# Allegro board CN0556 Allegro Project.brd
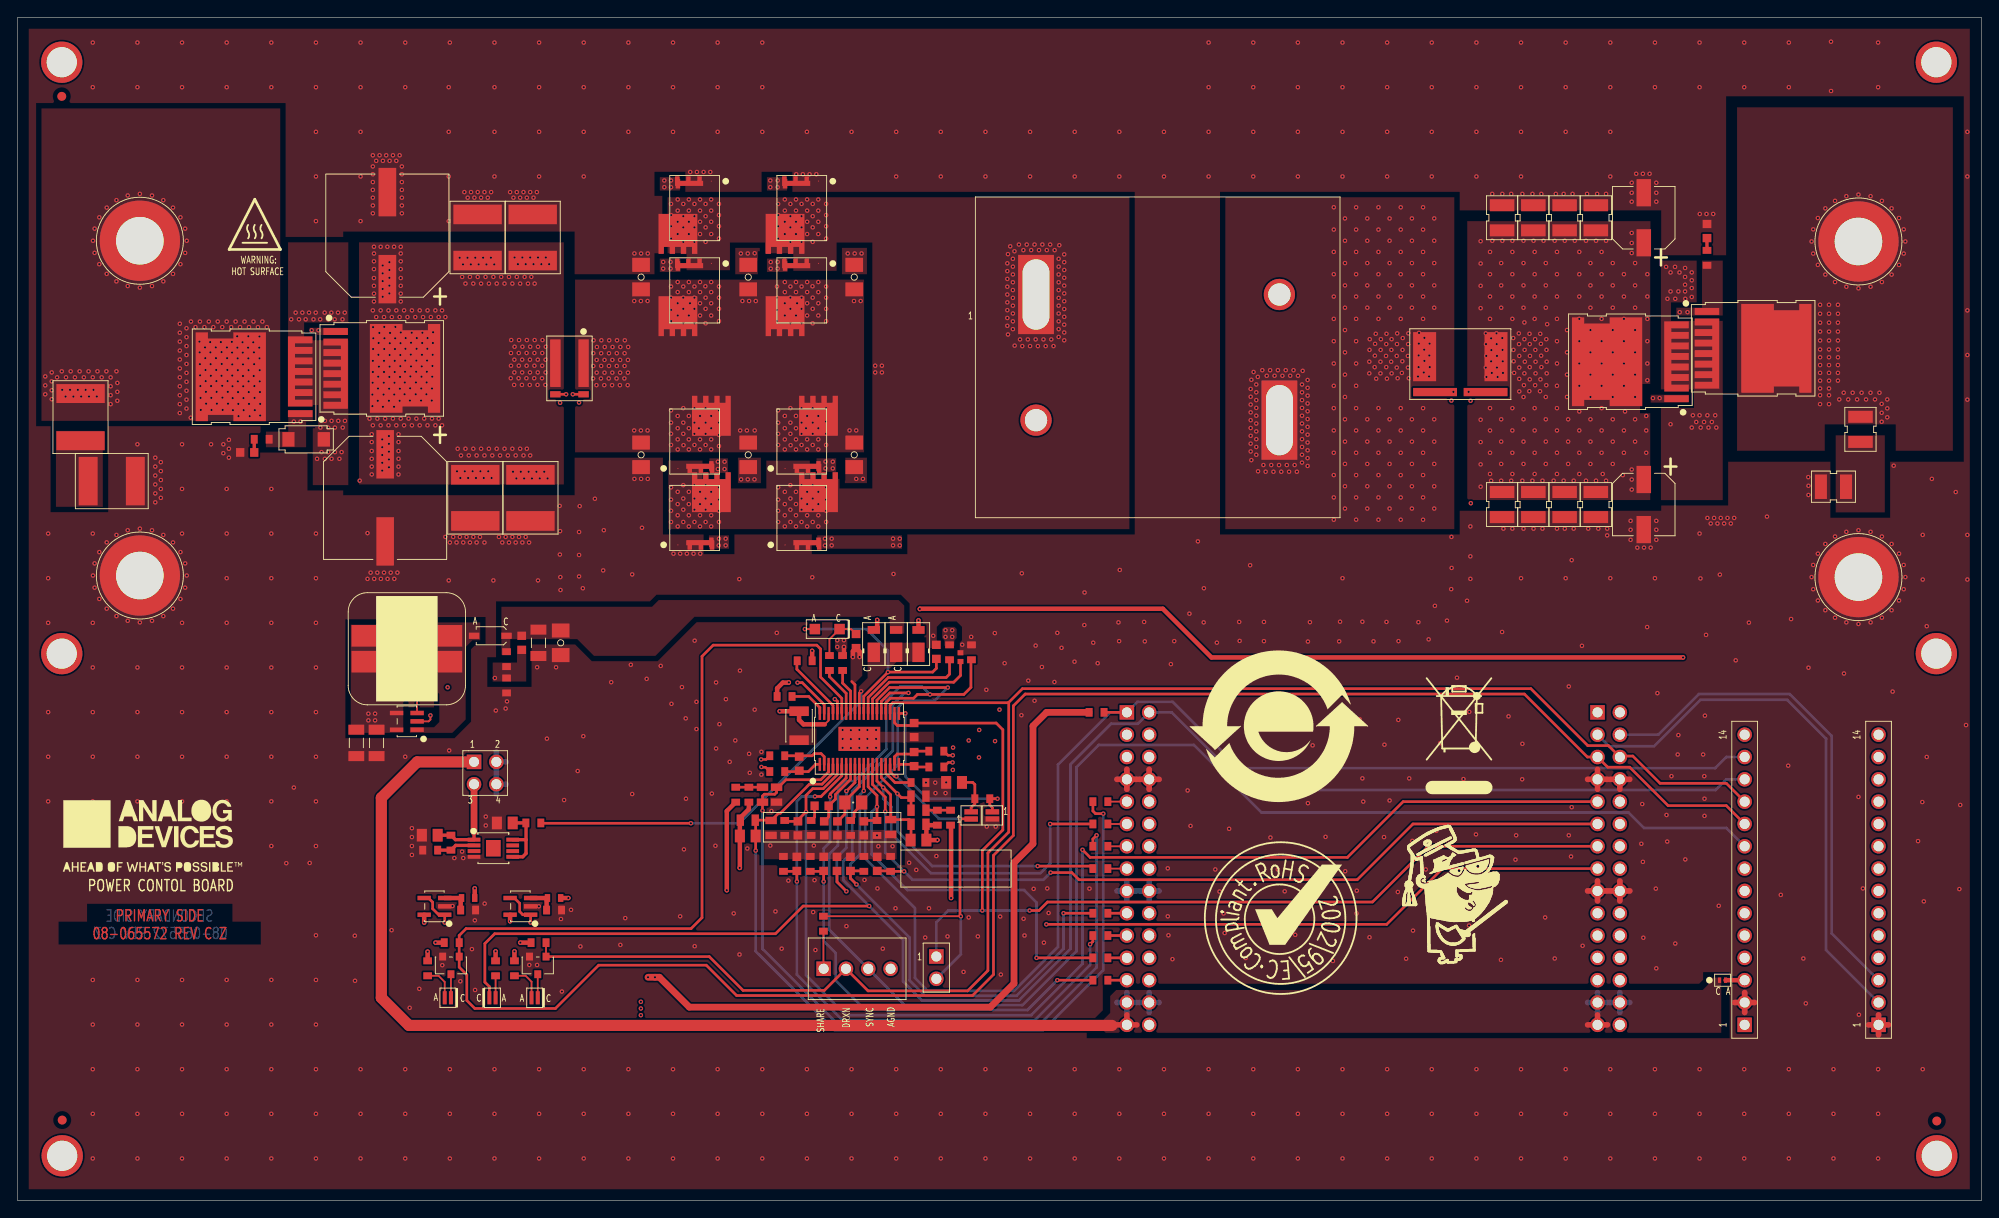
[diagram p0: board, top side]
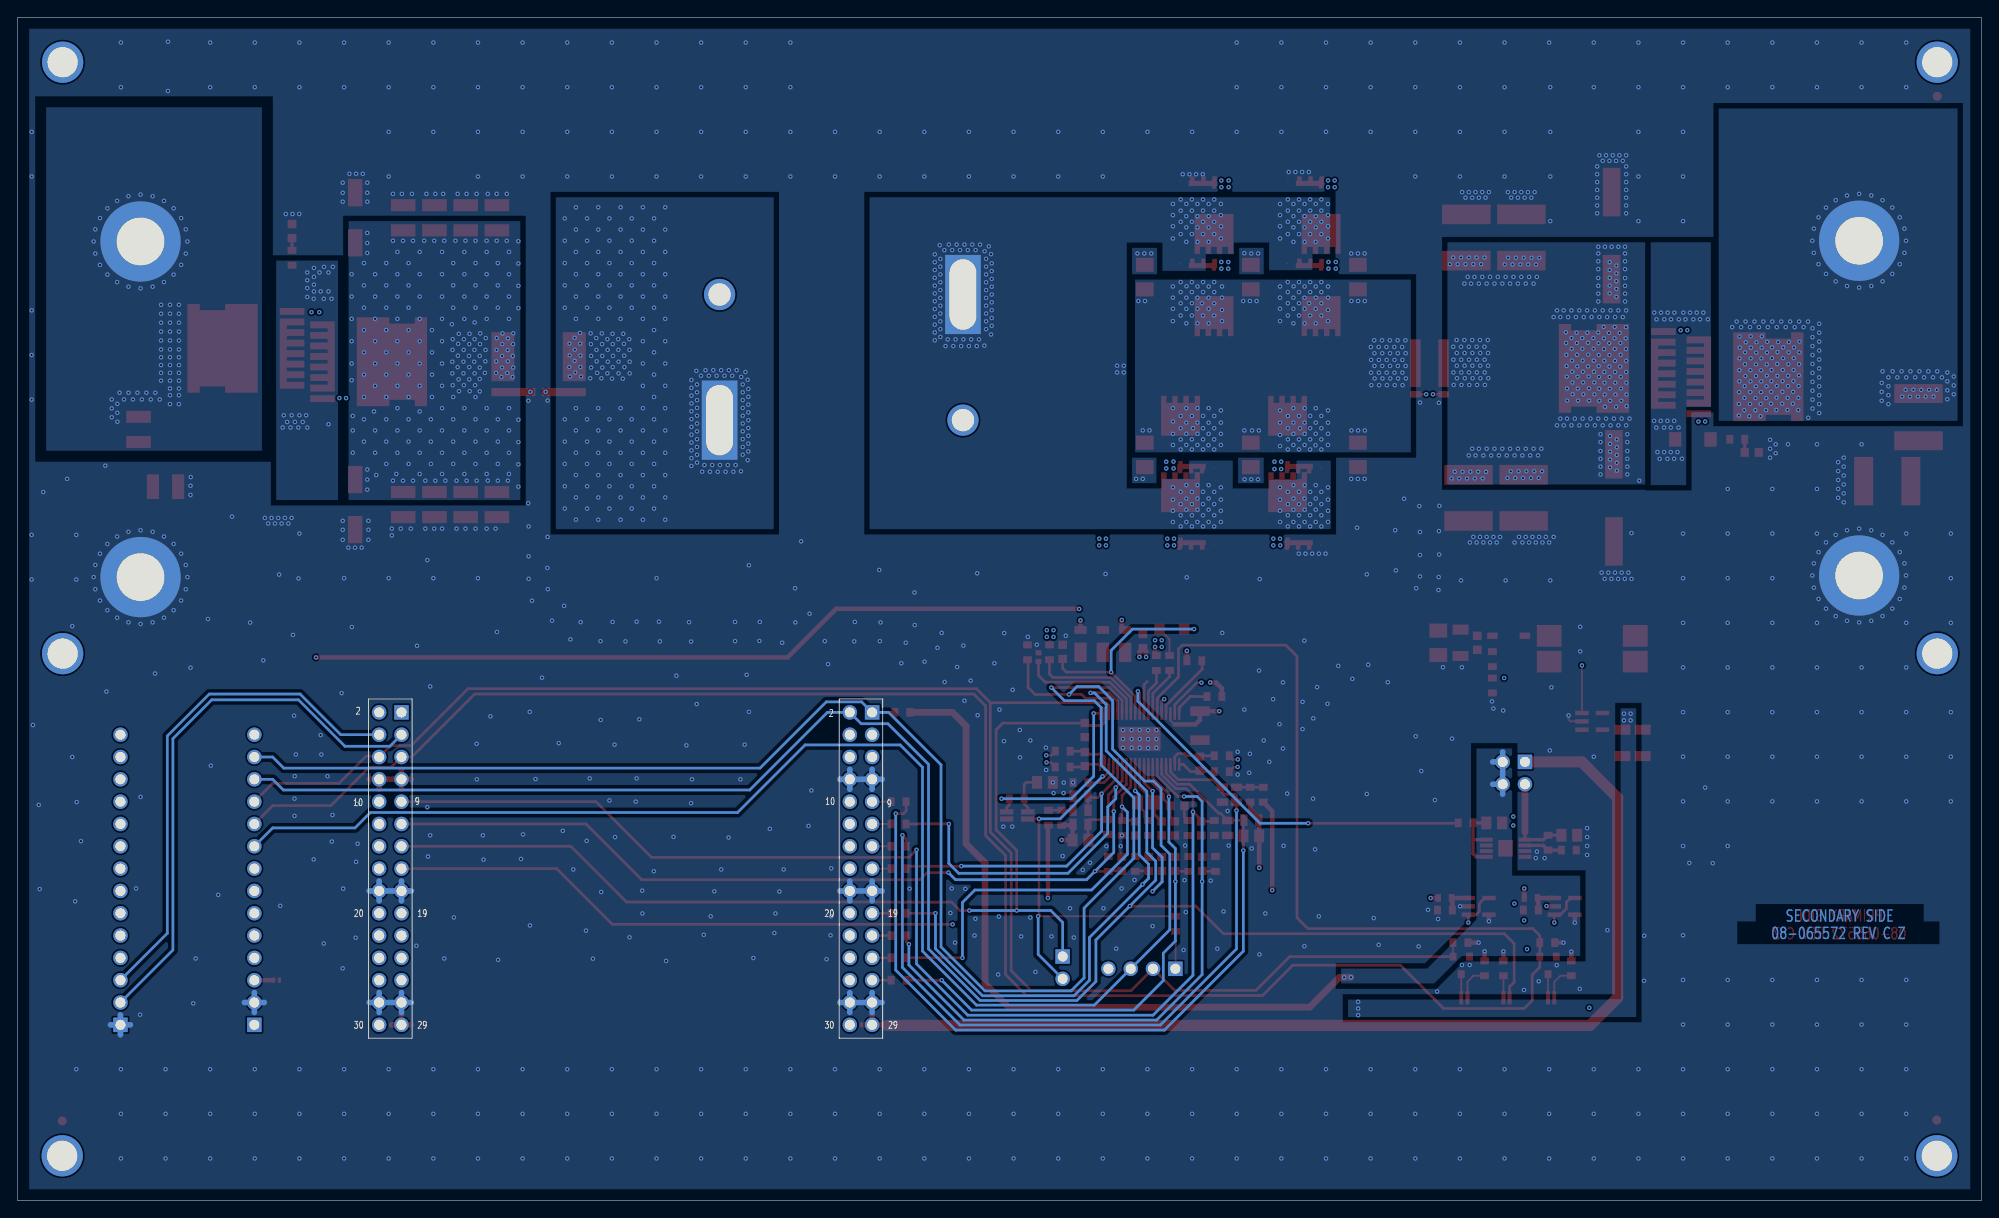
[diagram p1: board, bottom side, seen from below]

Outline 223.52 x 134.62 mm; copper layers: TOP, L2_GND, L3_PWR, BOTTOM. Coordinates in mm from the lower left corner of the outline.
Outline path: 0,134.62 0,0 223.52,0 223.52,134.62 0,134.62

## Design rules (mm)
constraint set DEFAULT: min track width 0.203
net group DP1_RSENSE1: nets UNNAMED_2_RES_I149_N1 UNNAMED_2_RES_I150_N1
net group DP2_RSENSE2: nets UNNAMED_2_RES_I147_N1 UNNAMED_2_RES_I148_N1
nets with their own width: min track width 0.203; nets UNNAMED_2_CAP_I281_N1

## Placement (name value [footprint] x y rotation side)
ADCCON  SSW-115-01-G-D  [CNRCPT2X15H335LD35]  179.83 55.55 270 bottom
BCKGND  575-4  [CNBANANAD312LD203]  209.52 70.94 0 top
BCKOUT  575-4  [CNBANANAD312LD203]  209.52 109.14 0 top
BSTGND  575-4  [CNBANANAD312LD203]  13.92 71.12 0 top
BSTOUT  575-4  [CNBANANAD312LD203]  13.92 109.22 0 top
C1  TBD  [C0603_0805]  83.11 41.48 0 top
C1N  0.01uF  [C0603]  88.7 38.3 90 top
C1P  0.01uF  [C0603]  94.79 38.3 90 top
C2  4.7uF  [C1210H87]  88.95 54.03 270 top
C2N  0.01uF  [C0603]  91.74 38.3 90 top
C2P  0.01uF  [C0603]  96.32 42.34 270 top
C3  1pF  [C0603]  88.96 49.71 90 top
C4  1pF  [C0603]  102.04 50.23 270 top
C5  1uF  [C0805]  55.45 42.96 180 top
C6  TBD  [C0603_0805]  102.54 41.01 180 top
C7  2.2uF  [C0805]  46.91 41.57 180 top
C8  2.2uF  [C1206]  38.56 52.07 270 top
C9  1uF  [C1206]  40.86 52.07 270 top
C10  10pF  [C0603]  57.38 63.46 270 top
C11  1uF  [C1206]  59.28 63.46 270 top
C12  4.7UF  [C1206H71]  61.82 63.46 270 top
CBST  0.1uF  [C0603]  95.43 63.67 90 top
CC1A  0.22uF  [C0603]  91.51 44.91 0 top
CC1B  220pF  [C0603]  91.82 42.34 90 top
CC2A  0.047uF  [C0805H60]  95.11 45.29 0 top
CC2B  470PF  [C0603]  93.32 42.34 270 top
CDG1  3300pF  [C0603]  26.14 85.13 180 top
CDG2  1000pF  [C0603]  192.28 110.32 90 top
CDM1_1  68UF  [CPLSMSQ531H551]  41.83 79.96 270 top
CDM1_2  68UF  [CPLSMSQ531H551]  42.09 109.8 90 top
CDM1_3  33UF  [CSML236W200H272]  52.36 109.59 270 top
CDM1_4  33UF  [CSML236W200H272]  58.63 109.59 90 top
CDM1_5  33UF  [CSML236W200H272]  52.1 79.96 90 top
CDM1_6  33UF  [CSML236W200H272]  58.38 79.96 270 top
CDM2_1  1uF  [C1206H71]  70.97 105.08 90 top
CDM2_2  1uF  [C1206H71]  83.16 105.08 90 top
CDM2_3  1uF  [C1206H71]  95.22 105.08 90 top
CDM2_4  1uF  [C1206H71]  70.97 84.86 270 top
CDM2_5  1uF  [C1206H71]  83.16 84.86 270 top
CDM2_6  1uF  [C1206H71]  95.22 84.86 270 top
CDM4_1  22UF  [C1210H110]  168.96 111.84 90 top
CDM4_2  22UF  [C1210H110]  172.52 111.84 90 top
CDM4_3  22UF  [C1210H110]  176.07 111.84 90 top
CDM4_4  22UF  [C1210H110]  179.63 111.84 90 top
CDM4_5  22UF  [C1210H110]  172.52 79.2 270 top
CDM4_6  22UF  [C1210H110]  168.96 79.2 270 top
CDM4_7  22UF  [C1210H110]  176.07 79.2 270 top
CDM4_8  22UF  [C1210H110]  179.63 79.2 270 top
CDM4_9  100uF  [CPLSMSQ260H315]  185.09 79.2 270 top
CDM4_X  100uF  [CPLSMSQ260H315]  185.09 111.84 90 top
CDRVCC  4.7uF  [C0603]  104.57 62.43 90 top
CINVCC  2.2uF  [C0603]  102.04 53.53 270 top
CMON1  0.01uF  [C0603]  88.81 42.34 270 top
CMON2  0.01uF  [C0603]  97.84 38.3 90 top
CSHARE  TBD  [C0603_0805]  106.59 47.57 180 top
CSS  0.1uF  [C0603]  93.27 38.3 90 top
CTMR  0.015uF  [C0402]  107.32 61.83 270 top
CV1_A  15uF  [C2220H264]  7.16 89.15 270 top
CV1_B  15uF  [C2220H264]  10.72 81.86 0 top
CV2_A  22UF  [C1210H110]  209.75 87.76 270 top
CV2_B  22UF  [C1210H110]  206.68 81.23 180 top
D1  DFLS1200Q-7  [POWERDI123]  100 63.32 90 top
D2  DFLS1200Q-7  [POWERDI123]  102.54 63.32 90 top
D3  DFLS1200Q-7  [POWERDI123]  97.46 63.32 90 top
D4  B0530W-7-F  [SOD123-3]  53.81 64.26 180 top
D5  BAT54LPS  [DFN2_1X0_6]  194.06 25.07 0 top
DACCON  SSW-115-01-G-D  [CNRCPT2X15H335LD35]  126.26 55.55 270 bottom
DBST  US1GWF-7  [SOD123F]  92.15 65.02 180 top
DS1  LXZ1-PM01  [LEDSML51W67H26]  48.97 23.06 180 top
DS2  LXZ1-PA01  [LEDSML51W67H26]  54.05 23.06 0 top
DS3  LXZ1-PB01  [LEDSML51W67H26]  58.85 23.06 180 top
DV1  SMAJ60CA  [DO214AC_C]  32.84 86.61 180 top
FB1CTL  11.3K  [R0603]  123.24 45.39 180 top
FB2CTL  8.66K  [R0603]  123.24 42.85 180 top
L1  10UH  [LTHL1417W1614H1378]  115.92 103.1 270 top
L2  10uH  [INDSUMCDRH125]  44.31 62.79 270 top
M1A  IPT007N06NATMA1  [HSOF8]  26.92 93.75 90 top
M1B  IPT007N06NATMA1  [HSOF8]  41.45 94.69 270 top
M2_1  IAUC70N08S5N074ATMA1  [SON8_FL]  77.06 86.37 0 top
M2_2  IAUC70N08S5N074ATMA1  [SON8_FL]  89.26 103.57 180 top
M2_3  IAUC70N08S5N074ATMA1  [SON8_FL]  77.06 103.57 180 top
M2_4  IAUC70N08S5N074ATMA1  [SON8_FL]  89.26 86.37 0 top
M3_1  IAUC70N08S5N074ATMA1  [SON8_FL]  77.06 77.67 0 top
M3_2  IAUC70N08S5N074ATMA1  [SON8_FL]  89.26 112.93 180 top
M3_3  IAUC70N08S5N074ATMA1  [SON8_FL]  77.06 112.93 180 top
M3_4  IAUC70N08S5N074ATMA1  [SON8_FL]  89.26 77.67 0 top
M4A  IPT007N06NATMA1  [HSOF8]  183.57 95.45 90 top
M4B  IPT007N06NATMA1  [HSOF8]  197.54 96.98 270 top
NOREF  -  []  -286.08 -132.38 0 top
NOREF#2  -  []  -106.07 273.65 0 top
NOREF#3  -  []  220.39 131.13 0 top
NOREF#4  -  []  -201.66 279.35 0 top
NOREF#5  -  []  67.11 26.24 0 top
NOREF#6  -  []  173.33 63.12 0 top
NOREF#7  -  []  0 0 0 top
NOREF#8  -  []  0 134.62 0 top
NOREF#9  -  []  -286.08 -132.38 0 top
NOREF#10  -  []  211.7 112.45 0 top
NOREF#11  -  []  55.75 267.72 0 top
NOREF#12  -  []  -107.56 263.49 0 top
NOREF#13  -  []  223.52 134.62 180 top
NOREF#14  -  []  143.51 53.97 0 top
NOREF#15  -  [unnamed#2]  5.03 62.23 0 top
NOREF#16  -  [unnamed#2]  218.44 5.08 0 top
NOREF#17  -  [unnamed#2]  5.03 129.54 0 top
NOREF#18  -  []  -25.45 -7.62 0 top
NOREF#19  -  []  48.97 19.94 0 top
NOREF#20  -  []  -201.81 273.65 0 top
NOREF#21  -  []  16.18 28.02 270 top
NOREF#22  -  []  5.08 5.08 0 top
NOREF#23  -  [unnamed#2]  218.39 129.54 0 top
NOREF#24  -  []  143.76 32 0 top
NOREF#25  -  []  223.52 0 90 top
NOREF#26  -  [unnamed#2]  218.44 9.04 0 top
NOREF#27  -  []  -25.45 -7.62 0 top
NOREF#28  -  []  5.08 5.08 0 top
NOREF#29  -  [unnamed#2]  5.08 9.14 0 top
NOREF#30  -  []  14.79 41.48 0 top
NOREF#31  -  []  243.89 279.6 0 top
NOREF#32  -  []  223.52 0 0 top
NOREF#33  -  []  -132.51 273.63 0 top
NOREF#34  -  []  223.52 0 90 top
NOREF#35  -  []  -75.36 268.55 0 top
NOREF#36  -  []  -286.08 -132.38 0 top
NOREF#37  -  []  0 0 0 top
NOREF#38  -  [unnamed#2]  5.03 125.65 0 top
NOREF#39  -  []  0 0 0 top
NOREF#40  -  []  261.8 64.47 0 top
NOREF#41  -  [unnamed#2]  5.08 5.08 0 top
NOREF#42  -  []  0 134.62 0 top
NOREF#43  -  []  119.3 364.57 0 top
NOREF#44  -  []  108.57 159.38 0 top
NOREF#45  -  [unnamed#2]  218.39 62.23 0 top
NOREF#46  -  []  -214.71 307.92 0 top
NOREF#47  -  []  -201.69 252.7 0 top
NOREF#48  -  []  0 134.62 270 top
NOREF#49  -  []  94.93 25.73 180 bottom
P1  TSW-102-07-T-D  [CNSAMTEC2X2H338LD36]  51.95 49.91 270 top
P2  SSQ-114-02-G-S  [CNTHFHDR1X14L1400W95H340]  211.81 19.99 90 top
P3  282834-4  [CN1X4H406]  95.55 26.37 0 top
P4  SSQ-114-02-G-S  [CNTHFHDR1X14L1400W95H340]  196.57 19.99 90 top
P5  TSW-102-07-G-S  [CNTHMHDR1X2L200W98H343]  104.57 27.76 270 top
P6  -  [JPSLD02]  108.53 43.81 90 top
P7  -  [JPSLD02]  110.95 43.81 270 top
Q1  2N7002-7-F  [SOT23-M3]  49.32 26.75 180 top
Q2  2N7002-7-F  [SOT23-M3]  59.21 26.75 180 top
R1  0  [R0603]  83.24 46.18 270 top
R1A  10K  [R0603]  51.28 33.05 0 top
R1B  243K  [R0603]  51.28 34.42 180 top
R1N  90.9K  [R0603]  87.17 38.3 90 top
R1P  90.9K  [R0603]  96.32 38.3 90 top
R2  0  [R0603]  81.74 46.18 270 top
R2A  10K  [R0603]  61.06 33.05 0 top
R2B  51K  [R0603]  61.06 34.42 180 top
R2N  26.1K  [R0603]  90.22 38.3 90 top
R2P  26.1K  [R0603]  97.82 42.39 270 top
R3  0  [R0603]  87.3 57.35 0 top
R4  0  [R0603]  91.72 31.5 90 top
R5  0  [R0603]  92.4 61.16 270 top
R6  1  [R0603]  106.07 62.38 270 top
R7  1  [R0603]  93.9 61.16 270 top
R8  0  [R0603]  89.59 61.42 0 top
R9  0  [R0603]  58.7 42.97 180 top
R10  499K  [R0603]  49.33 40.72 270 top
R11  316K  [R0603]  46.96 39.87 180 top
R13  0  [R0603]  106.19 43.56 90 top
R14  0  [R0603]  104.69 43.56 90 top
R16  115K  [R0603]  55.65 61.61 270 top
R17  13.3K  [R0603]  55.65 58.61 270 top
R22  4.99K  [R0603]  46.67 26.42 270 top
R23  6.65K  [R0603]  122.81 55.55 0 top
R24  1.21M  [R0603]  59.3 29.34 0 top
R25  4.99K  [R0603]  54.41 26.42 270 top
R26  22.1K  [R0603]  49.41 29.34 0 top
R27  4.99K  [R0603]  56.55 26.42 270 top
RC1  1K  [R0603]  90.32 42.39 90 top
RC2  1K  [R0603]  94.82 42.39 270 top
RCTL1N  665K  [R0603]  123.24 30.15 180 top
RCTL1P  665K  [R0603]  123.24 32.69 180 top
RCTL2N  187K  [R0603]  123.24 25.07 180 top
RCTL2P  187K  [R0603]  123.24 27.61 180 top
RDG1  10K  [R0603]  27.79 86.63 180 top
RDG2  10K  [R0603]  192.28 107.27 90 top
RFB1A  54.9K  [R0805]  83.11 43.28 0 top
RFB1B  1.21K  [R0805]  85.76 42.39 270 top
RFB2A  12.7K  [R0805]  102.54 42.81 180 top
RFB2B  1.21K  [R0805]  99.37 42.49 270 top
RIN1A  1.5K  [R0603]  86.46 48.81 0 top
RIN1B  1.5K  [R0603]  86.46 50.61 0 top
RIN2A  1.5K  [R0603]  104.57 51.13 180 top
RIN2B  1.5K  [R0603]  104.57 49.33 180 top
RMON1  187K  [R0603]  87.31 42.39 270 top
RMON2  53.6K  [R0603]  99.36 38.3 90 top
RSHARE  0  [R0603]  109.8 45.72 0 top
RSNS1  0.002  [R2512-4P]  62.81 94.69 270 top
RSNS2  0.002  [RSML260W396H123]  164.21 95.17 90 top
RSYNC  100K  [R0603]  108.57 62.38 90 top
RT  68K  [R0603]  102.54 47.56 0 top
RUV1A  52.3K  [R0805]  84.79 46.18 270 top
RUV1B  1.21K  [R0805]  86.39 46.18 270 top
RUV2A  10K  [R0805]  102.54 44.41 180 top
RUV2B  1.21K  [R0805]  102.54 46.01 0 top
U1  LT8228EFE#PBF  [TSSOP38_PAD4_75X2_74]  95.81 52.53 0 top
U2  LT3010EMS8E#PBF  [MSOP8_PAD1_88X1_68]  54.15 40.08 270 top
U3  LT1930ES5#TRPBF  [TSOT-5]  44.31 54.52 90 top
U4  ADA4505-1ARJZ  [SOT23-5L]  47.45 33.47 90 top
U5  ADA4505-1ARJZ  [SOT23-5L]  57.23 33.47 90 top
UV1CTL  10.2K  [R0603]  123.24 40.31 0 top
UV2CTL  8.2K  [R0603]  123.24 37.77 180 top

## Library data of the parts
ADCCON DACCON = CN30P_ODD_EVEN_V2: Tolerance: N/A; User Part Number: UPN; alternate symbols: (CNRCPT2X15H335LD35); part number: CN30P_ODD_EVEN_V2_TH-SSW-115-01-G-D,E012831,CNRCPT2X15H335LD35; tolerance: N/A
BCKGND BCKOUT BSTGND BSTOUT = CNTP1P: Tolerance: N/A; User Part Number: UPN; alternate symbols: (CNBANANAD312LD203); part number: CNTP1P_TH-575-4,E012555,CNBANANAD312LD203; tolerance: N/A
C1 C6 CSHARE = CAP: User Part Number: UPN; Tolerance: N/A; alternate symbols: (C0603_0805); part number: CAP_SM-TBD,N/A,N/A,E029810,C0603_0805; tolerance: N/A
C1N C1P C2N C2P CMON1 CMON2 = CAP: User Part Number: UPN; Tolerance: 10; alternate symbols: (C0603); part number: CAP_SM-0.01UF,50V,10,E038603,C0603; tolerance: 10
C2 = CAP: Tolerance: 10; User Part Number: UPN; alternate symbols: (C1210H87); part number: CAP_SM-4.7UF,100V,10,E023932,C1210H87; tolerance: 10
C3 C4 = CAP: User Part Number: UPN; Tolerance: 0.1pF; alternate symbols: (C0603); part number: CAP_SM-1PF,100V,0.1PF,E013795,C0603; tolerance: 0.1pF
C5 = CAP: User Part Number: UPN; Tolerance: 10; alternate symbols: (C0805); part number: CAP_SM-1UF,100V,10,E014208,C0805; tolerance: 10
C7 = CAP: User Part Number: UPN; Tolerance: 10; alternate symbols: (C0805); part number: CAP_SM-2.2UF,10V,10,E010425,C0805; tolerance: 10
C8 = CAP: User Part Number: UPN; Tolerance: 10; alternate symbols: (C1206); part number: CAP_SM-2.2UF,16V,10,E033858,C1206; tolerance: 10
C9 C11 = CAP: User Part Number: UPN; Tolerance: 10; alternate symbols: (C1206); part number: CAP_SM-1UF,25V,10,E029793,C1206; tolerance: 10
C10 = CAP: User Part Number: UPN; Tolerance: 5; alternate symbols: (C0603); part number: CAP_SM-10PF,50V,5,E031564,C0603; tolerance: 5
C12 = CAP: Tolerance: 10; User Part Number: UPN; alternate symbols: (C1206H71); part number: CAP_SM-4.7UF,16V,10,E042795,C1206H71; tolerance: 10
CBST = CAP: User Part Number: UPN; Tolerance: 10; alternate symbols: (C0603); part number: CAP_SM-0.1UF,50V,10,E031623,C0603; tolerance: 10
CC1A = CAP: User Part Number: UPN; Tolerance: 10; alternate symbols: (C0603); part number: CAP_SM-0.22UF,50V,10,E015565,C0603; tolerance: 10
CC1B = CAP: User Part Number: UPN; Tolerance: 5; alternate symbols: (C0603); part number: CAP_SM-220PF,50V,5,E042972,C0603; tolerance: 5
CC2A = CAP: Tolerance: 10; User Part Number: UPN; alternate symbols: (C0805H60); part number: CAP_SM-0.047UF,100V,10,E030859,C0805H60; tolerance: 10
CC2B = CAP: User Part Number: UPN; Tolerance: 10; alternate symbols: (C0603); part number: CAP_SM-470PF,25V,10,E044224,C0603; tolerance: 10
CDG1 = CAP: User Part Number: UPN; Tolerance: 10; alternate symbols: (C0603); part number: CAP_SM-3300PF,50V,10,E030855,C0603; tolerance: 10
CDG2 = CAP: User Part Number: UPN; Tolerance: 5; alternate symbols: (C0603); part number: CAP_SM-1000PF,100V,5,E012694,C0603; tolerance: 5
CDM1_1 CDM1_2 = CAPP: Tolerance: 20; User Part Number: UPN; alternate symbols: (CPLSMSQ531H551); part number: CAPP_SM-68UF,100V,20,E042912,CPLSMSQ531H551; tolerance: 20
CDM1_3-CDM1_6 = CAP: User Part Number: UPN; Tolerance: 22; alternate symbols: (CSML236W200H272); part number: CAP_SM-33UF,100V,22,E043544,CSML236W200H272; tolerance: 22
CDM2_1-CDM2_6 = CAP: Tolerance: 10; User Part Number: UPN; alternate symbols: (C1206H71); part number: CAP_SM-1UF,100V,10,E044891,C1206H71; tolerance: 10
CDM4_1-CDM4_8 CV2_A CV2_B = CAP: Tolerance: 20; User Part Number: UPN; alternate symbols: (C1210H110); part number: CAP_SM-22UF,25V,20,E044311,C1210H110; tolerance: 20
CDM4_9 CDM4_X = CAPP: Tolerance: 20; User Part Number: UPN; alternate symbols: (CPLSMSQ260H315); part number: CAPP_SM-100UF,25V,20,E027144,CPLSMSQ260H315; tolerance: 20
CDRVCC = CAP: User Part Number: UPN; Tolerance: 10; alternate symbols: (C0603); part number: CAP_SM-4.7UF,16V,10,E020112,C0603; tolerance: 10
CINVCC = CAP: User Part Number: UPN; Tolerance: 10; alternate symbols: (C0603); part number: CAP_SM-2.2UF,10V,10,E015288,C0603; tolerance: 10
CSS = CAP: User Part Number: UPN; Tolerance: 10; alternate symbols: (C0603); part number: CAP_SM-0.1UF,50V,10,E030853,C0603; tolerance: 10
CTMR = CAP: User Part Number: UPN; Tolerance: 10; alternate symbols: (C0402); part number: CAP_SM-0.015UF,35V,10,E033385,C0402; tolerance: 10
CV1_A CV1_B = CAP: User Part Number: UPN; Tolerance: 20; alternate symbols: (C2220H264); part number: CAP_SM-15UF,100V,20,E030670,C2220H264; tolerance: 20
D1-D3 = DIOSCHOTTKY: User Part Number: UPN; Tolerance: N/A; alternate symbols: (POWERDI123); part number: DIOSCHOTTKY_SM-DFLS1200Q-7,200V,N/A,E034778,POWERDI123; tolerance: N/A
D4 = DIOSCHOTTKY: Tolerance: N/A; User Part Number: UPN; alternate symbols: (SOD123-3); part number: DIOSCHOTTKY_SM-B0530W-7-F,30V,N/A,E014780,SOD123-3; tolerance: N/A
D5 = DIOSCHOTTKY: Tolerance: N/A; User Part Number: UPN; alternate symbols: (DFN2_1X0_6); part number: DIOSCHOTTKY_SM-BAT54LPS,30V,N/A,E023691,DFN2_1X0_6; tolerance: N/A
DBST = DIO: Tolerance: N/A; User Part Number: UPN; alternate symbols: (SOD123F); part number: DIO_SM-US1GWF-7,400V,N/A,E042975,SOD123F; tolerance: N/A
DS1 = DIOLED: User Part Number: UPN; Tolerance: N/A; alternate symbols: (LEDSML51W67H26); part number: DIOLED_SM-LXZ1-PM01,N/A,N/A,E024055,LEDSML51W67H26; tolerance: N/A
DS2 = DIOLED: User Part Number: UPN; Tolerance: N/A; alternate symbols: (LEDSML51W67H26); part number: DIOLED_SM-LXZ1-PA01,2.2V,N/A,E033979,LEDSML51W67H26; tolerance: N/A
DS3 = DIOLED: User Part Number: UPN; Tolerance: N/A; alternate symbols: (LEDSML51W67H26); part number: DIOLED_SM-LXZ1-PB01,2.85V,N/A,E033980,LEDSML51W67H26; tolerance: N/A
DV1 = DIOZNR_V2: User Part Number: UPN; Tolerance: 5; alternate symbols: (DO214AC_C); part number: DIOZNR_V2_SM-SMAJ60CA,60V,5,E044927,DO214AC_C; tolerance: 5
FB1CTL = RES: User Part Number: UPN; Tolerance: 1; alternate symbols: (R0603); part number: RES_SM-11.3K,E027487,1/10W,1,R0603; tolerance: 1
FB2CTL = RES: User Part Number: UPN; Tolerance: 1; alternate symbols: (R0603); part number: RES_SM-8.66K,E017718,1/10W,1,R0603; tolerance: 1
L1 = IND: Tolerance: 20; User Part Number: UPN; alternate symbols: (LTHL1417W1614H1378); part number: IND_TH-10UH,20,E043963,LTHL1417W1614H1378; tolerance: 20
L2 = IND_4P: Tolerance: 20; User Part Number: UPN; alternate symbols: (INDSUMCDRH125); part number: IND_4P_SM-10UH,20,E007395,INDSUMCDRH125; tolerance: 20
M1A M1B M4A M4B = TRANNMOSFET9P: User Part Number: UPN; Tolerance: N/A; alternate symbols: (HSOF8); part number: TRANNMOSFET9P_SM-IPT007N06NATMA1,E047026,HSOF8; tolerance: N/A
M2_1-M2_4 M3_1-M3_4 = TRANNMOSFET8P: Tolerance: N/A; User Part Number: UPN; alternate symbols: (SON8_FL); part number: TRANNMOSFET8P_SM-IAUC70N08S5N074ATMA1,E043073,SON8_FL; tolerance: N/A
P1 = CN4P_ODD_EVEN: User Part Number: UPN; Tolerance: N/A; alternate symbols: (CNSAMTEC2X2H338LD36); part number: CN4P_ODD_EVEN_TH-TSW-102-07-T-D,E032495,CNSAMTEC2X2H338LD36; tolerance: N/A
P2 P4 = CN14P: User Part Number: UPN; Tolerance: N/A; alternate symbols: (CNTHFHDR1X14L1400W95H340); part number: CN14P_TH-SSQ-114-02-G-S,E026120,CNTHFHDR1X14L1400W95H340; tolerance: N/A
P3 = CN4P: Tolerance: N/A; User Part Number: UPN; alternate symbols: (CN1X4H406); part number: CN4P_TH-282834-4,E016935,CN1X4H406; tolerance: N/A
P5 = CN2P: User Part Number: UPN; Tolerance: N/A; alternate symbols: (CNTHMHDR1X2L200W98H343); part number: CN2P_TH-TSW-102-07-G-S,E031850,CNTHMHDR1X2L200W98H343; tolerance: N/A
P6 P7 = NC2P: User Part Number: UPN; Tolerance: N/A; alternate symbols: (JPSLD02); part number: NC2P_SM-JPSLD02,E006230,JPSLD02; tolerance: N/A
Q1 Q2 = TRAN2N7002: User Part Number: UPN; Tolerance: N/A; alternate symbols: (SOT23-M3); part number: TRAN2N7002_SM-2N7002-7-F,E019273,SOT23-M3; tolerance: N/A
R1-R5 R8 R9 R13 R14 RSHARE = RES: User Part Number: UPN; Tolerance: JUMPER; alternate symbols: (R0603); part number: RES_SM-0,E006826,1/10W,JUMPER,R0603; tolerance: JUMPER
R1A R2A RDG1 RDG2 = RES: User Part Number: UPN; Tolerance: 1; alternate symbols: (R0603); part number: RES_SM-10K,E003671,1/10W,1,R0603; tolerance: 1
R1B = RES: User Part Number: UPN; Tolerance: 1; alternate symbols: (R0603L); part number: RES_SM-243K,E029637,1/10W,1,R0603; tolerance: 1
R1N R1P = RES: User Part Number: UPN; Tolerance: 1; alternate symbols: (R0603); part number: RES_SM-90.9K,E003723,1/10W,1,R0603; tolerance: 1
R2B = RES: User Part Number: UPN; Tolerance: 1; alternate symbols: (R0603L); part number: RES_SM-51K,E014698,1/10W,1,R0603; tolerance: 1
R2N R2P = RES: User Part Number: UPN; Tolerance: 1; alternate symbols: (R0603); part number: RES_SM-26.1K,E024699,1/10W,1,R0603; tolerance: 1
R6 R7 = RES: User Part Number: UPN; Tolerance: 5; alternate symbols: (R0603); part number: RES_SM-1,E011738,1/10W,5,R0603; tolerance: 5
R10 = RES: User Part Number: UPN; Tolerance: 1; alternate symbols: (R0603); part number: RES_SM-499K,E015340,1/10W,1,R0603; tolerance: 1
R11 = RES: User Part Number: UPN; Tolerance: 1; alternate symbols: (R0603); part number: RES_SM-316K,E027926,1/10W,1,R0603; tolerance: 1
R16 = RES: User Part Number: UPN; Tolerance: 1; alternate symbols: (R0603); part number: RES_SM-115K,E021375,1/10W,1,R0603; tolerance: 1
R17 = RES: User Part Number: UPN; Tolerance: 1; alternate symbols: (R0603); part number: RES_SM-13.3K,E008069,1/10W,1,R0603; tolerance: 1
R22 R25 R27 = RES: User Part Number: UPN; Tolerance: 1; alternate symbols: (R0603); part number: RES_SM-4.99K,E003726,1/10W,1,R0603; tolerance: 1
R23 = RES: User Part Number: UPN; Tolerance: 1; alternate symbols: (R0603); part number: RES_SM-6.65K,E023334,1/10W,1,R0603; tolerance: 1
R24 = RES: User Part Number: UPN; Tolerance: 1; alternate symbols: (R0603); part number: RES_SM-1.21M,E063409,1/10W,1,R0603; tolerance: 1
R26 = RES: User Part Number: UPN; Tolerance: 1; alternate symbols: (R0603); part number: RES_SM-22.1K,E003681,1/10W,1,R0603; tolerance: 1
RC1 RC2 = RES: User Part Number: UPN; Tolerance: 1; alternate symbols: (R0603); part number: RES_SM-1K,E003678,1/10W,1,R0603; tolerance: 1
RCTL1N RCTL1P = RES: User Part Number: UPN; Tolerance: 1; alternate symbols: (R0603); part number: RES_SM-665K,E063003,1/10W,1,R0603; tolerance: 1
RCTL2N RCTL2P RMON1 = RES: User Part Number: UPN; Tolerance: 1; alternate symbols: (R0603); part number: RES_SM-187K,E032773,1/10W,1,R0603; tolerance: 1
RFB1A = RES: User Part Number: UPN; Tolerance: 1; alternate symbols: (R0805L); part number: RES_SM-54.9K,E033779,1/8W,1,R0805; tolerance: 1
RFB1B RFB2B RUV1B RUV2B = RES: User Part Number: UPN; Tolerance: 1; alternate symbols: (R0805L); part number: RES_SM-1.21K,E003483,1/8W,1,R0805; tolerance: 1
RFB2A = RES: User Part Number: UPN; Tolerance: 1; alternate symbols: (R0805L); part number: RES_SM-12.7K,E015005,1/8W,1,R0805; tolerance: 1
RIN1A RIN1B RIN2A RIN2B = RES: User Part Number: UPN; Tolerance: 1; alternate symbols: (R0603); part number: RES_SM-1.5K,E003704,1/10W,1,R0603; tolerance: 1
RMON2 = RES: User Part Number: UPN; Tolerance: 1; alternate symbols: (R0603); part number: RES_SM-53.6K,E027826,1/10W,1,R0603; tolerance: 1
RSNS1 = RES4PKEL_V6: User Part Number: UPN; Tolerance: 2; alternate symbols: (R2512-4P); part number: RES4PKEL_V6_SM-0.002,E063408,2W,2,R2512-4P; tolerance: 2
RSNS2 = RES4PKEL_V7: Tolerance: 1; User Part Number: UPN; alternate symbols: (RSML260W396H123_A); part number: RES4PKEL_V7_SM-0.002,E043111,4W,1,RSML260W396H123; tolerance: 1
RSYNC = RES: User Part Number: UPN; Tolerance: 1; alternate symbols: (R0603); part number: RES_SM-100K,E010279,1/10W,1,R0603; tolerance: 1
RT = RES: User Part Number: UPN; Tolerance: 1; alternate symbols: (R0603); part number: RES_SM-68K,E031013,1/10W,1,R0603; tolerance: 1
RUV1A = RES: User Part Number: UPN; Tolerance: 1; alternate symbols: (R0805L); part number: RES_SM-52.3K,E028373,1/8W,1,R0805; tolerance: 1
RUV2A = RES: User Part Number: UPN; Tolerance: 1; alternate symbols: (R0805L); part number: RES_SM-10K,E003254,1/8W,1,R0805; tolerance: 1
U1 = ADLT8228: User Part Number: UPN; Tolerance: N/A; alternate symbols: (TSSOP38_PAD4_75X2_74); part number: ADLT8228_SM-LT8228EFE#PBF,E045130,TSSOP38_PAD4_75X2_74; tolerance: N/A
U2 = ADLT3010: Tolerance: N/A; User Part Number: UPN; alternate symbols: (MSOP8_PAD1_88X1_68); part number: ADLT3010_SM-LT3010EMS8E#PBF,E043304,MSOP8_PAD1_88X1_68; tolerance: N/A
U3 = LINLT1930: User Part Number: UPN; Tolerance: N/A; alternate symbols: (TSOT-5); part number: LINLT1930_SM-LT1930ES5#TRPBF,E030333,TSOT-5; tolerance: N/A
U4 U5 = AD8677: User Part Number: UPN; Tolerance: N/A; alternate symbols: (SOT23-5L); part number: AD8677_SM-ADA4505-1ARJZ,E015633,SOT23-5L; tolerance: N/A
UV1CTL = RES: User Part Number: UPN; Tolerance: 1; alternate symbols: (R0603); part number: RES_SM-10.2K,E013703,1/10W,1,R0603; tolerance: 1
UV2CTL = RES: User Part Number: UPN; Tolerance: 1; alternate symbols: (R0603); part number: RES_SM-8.2K,E042863,1/10W,1,R0603; tolerance: 1

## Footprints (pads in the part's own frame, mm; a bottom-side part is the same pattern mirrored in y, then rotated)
C0402
  rect 0.584x0.66 smd: 1(-0.5,0) 2(0.5,0)
C0603
  rect 0.94x0.991 smd: 1(-0.8,0) 2(0.8,0)
C0603_0805
  rect 1.143x1.448 smd: 1(-0.9,0) 2(0.9,0)
C0805
  rect 1.143x1.448 smd: 1(-0.9,0) 2(0.9,0)
C0805H60
  rect 1.295x1.6 smd: 1(-0.953,0) 2(0.953,0)
C1206
  rect 1.143x1.803 smd: 1(-1.5,0) 2(1.5,0)
C1206H71
  rect 1.6x2.007 smd: 1(-1.397,0) 2(1.397,0)
C1210H87
  rect 1.092x2.21 smd: 1(-1.646,0) 2(1.646,0)
C1210H110
  rect 1.372x2.794 smd: 1(-1.431,0) 2(1.431,0)
C2220H264
  rect 2.159x5.512 smd: 1(-2.685,0) 2(2.685,0)
CN1X4H406
  rect 1.651x1.651 hole 1.143: 1(-3.81,0)
  round 1.651 hole 1.143: 2(-1.27,0) 3(1.27,0) 4(3.81,0)
CNBANANAD312LD203
  round 9.144 hole 5.41: 1(0,0)
CNRCPT2X15H335LD35
  rect 1.651x1.651 hole 1.143: 1(0,0)
  round 1.651 hole 1.143: 2(0,-2.54) 3(2.54,0) 4(2.54,-2.54) 5(5.08,0) 6(5.08,-2.54) 7(7.62,0) 8(7.62,-2.54) 9(10.16,0) 10(10.16,-2.54) 11(12.7,0) 12(12.7,-2.54) 13(15.24,0) 14(15.24,-2.54) 15(17.78,0) 16(17.78,-2.54) 17(20.32,0) 18(20.32,-2.54) 19(22.86,0) 20(22.86,-2.54) 21(25.4,0) 22(25.4,-2.54) 23(27.94,0) 24(27.94,-2.54) 25(30.48,0) 26(30.48,-2.54) 27(33.02,0) 28(33.02,-2.54) 29(35.56,0) 30(35.56,-2.54)
CNSAMTEC2X2H338LD36
  rect 1.651x1.651 hole 1.143: 1(0,0)
  round 1.651 hole 1.143: 2(0,2.54) 3(2.54,0) 4(2.54,2.54)
CNTHFHDR1X14L1400W95H340
  rect 1.651x1.651 hole 1.143: 1(0,0)
  round 1.651 hole 1.143: 2(2.54,0) 3(5.08,0) 4(7.62,0) 5(10.16,0) 6(12.7,0) 7(15.24,0) 8(17.78,0) 9(20.32,0) 10(22.86,0) 11(25.4,0) 12(27.94,0) 13(30.48,0) 14(33.02,0)
CNTHMHDR1X2L200W98H343
  rect 1.651x1.651 hole 1.143: 1(0,0)
  round 1.651 hole 1.143: 2(2.54,0)
CPLSMSQ260H315
  rect 3.099x1.651 smd: N(2.85,0) P(-2.85,0)
CPLSMSQ531H551
  rect 5.512x2.007 smd: N(4.956,0) P(-4.956,0)
CSML236W200H272
  rect 2.235x5.512 smd: 1(-2.628,0) 2(2.628,0)
DFN2_1X0_6
  rect 0.356x0.61 smd: A(0.34,0) C(-0.34,0)
DO214AC_C
  rect 1.397x1.651 smd: 1(-2.013,0) 2(2.013,0)
HSOF8
  rect 0.787x2.794 smd: 1(-4.2,-5.253)
  round 0.254 smd: 2(-3,-5.253) 3(-1.8,-5.253) 4(-0.6,-5.253) 6(1.8,-5.253) 7(3,-5.253) 8(4.2,-5.253)
  custom 0.699x0.699 smd: 5(0.6,-5.253)
  custom 2x2 smd: 9(0,2.649)
INDSUMCDRH125
  rect 2.464x2.819 smd: 1(-1.469,-4.897) 2(1.469,-4.897) 3(1.469,4.897) 4(-1.469,4.897)
JPSLD02
  rect 0.61x1.549 smd: 1(-0.406,0) 2(0.406,0)
LEDSML51W67H26
  rect 0.457x1.499 smd: A(0.354,0) C(-0.354,0)
LTHL1417W1614H1378
  round 3.556 hole 2.54: (0,27.7) (14.3,0)
  rect 9.017x4.064 hole 8.001x3.048: 1(0,0) 2(14.3,27.7)
MSOP8_PAD1_88X1_68
  rect 0.457x1.448 smd: 1(-0.975,-2.2) 2(-0.325,-2.2) 3(0.325,-2.2) 4(0.975,-2.2) 5(0.975,2.2) 6(0.325,2.2) 7(-0.325,2.2) 8(-0.975,2.2)
  rect 1.88x1.676 smd: PAD(0,0)
POWERDI123
  rect 0.889x1.397 smd: A(1.606,0)
  rect 2.21x1.397 smd: C(-0.945,0)
R0603
  rect 0.787x0.991 smd: 1(-0.85,0) 2(0.85,0)
R0805
  rect 0.838x1.295 smd: 1(-0.85,0) 2(0.85,0)
R2512-4P
  rect 5.41x1.194 smd: 1(-0.595,1.603) 2(-0.595,-1.603)
  rect 0.711x1.194 smd: 3(2.944,1.603) 4(2.944,-1.603)
RSML260W396H123
  rect 5.588x2.616 smd: F1(0.851,-4.064) F2(0.851,4.064)
  rect 0.94x4.991 smd: S1(-3.175,-2.875) S2(-3.175,2.875)
SOD123-3
  rect 1.194x0.711 smd: A(1.847,0) C(-1.847,0)
SOD123F
  rect 1.194x1.194 smd: A(1.403,0) C(-1.403,0)
SON8_FL
  round 0.127 smd: 1(-1.905,-3.071) 2(-0.635,-3.071) 6(0.635,2.931) 7(-0.635,2.931) 8(-1.905,2.931)
  custom 0.273x0.273 smd: 3(0.635,-3.071)
  rect 0.508x1.092 smd: 4(1.905,-2.779)
  custom 1.105x1.105 smd: 5(1.905,2.931)
SOT23-5L
  rect 0.508x1.524 smd: 1(-0.95,-1.17) 2(0,-1.17) 3(0.95,-1.17) 4(0.95,1.17) 5(-0.95,1.17)
SOT23-M3
  rect 0.787x0.889 smd: 1(-0.94,-1.003) 2(0.94,-1.003) 3(0,1.003)
TSOT-5
  rect 0.508x1.524 smd: 1(-0.95,-1.17) 2(0,-1.17) 3(0.95,-1.17) 4(0.95,1.17) 5(-0.95,1.17)
TSSOP38_PAD4_75X2_74
  rect 0.279x1.473 smd: 1(-4.5,-2.9) 2(-4,-2.9) 3(-3.5,-2.9) 4(-3,-2.9) 5(-2.5,-2.9) 6(-2,-2.9) 7(-1.5,-2.9) 8(-1,-2.9) 9(-0.5,-2.9) 10(0,-2.9) 11(0.5,-2.9) 12(1,-2.9) 13(1.5,-2.9) 14(2,-2.9) 15(2.5,-2.9) 16(3,-2.9) 17(3.5,-2.9) 18(4,-2.9) 19(4.5,-2.9) 20(4.5,2.9) 21(4,2.9) 22(3.5,2.9) 23(3,2.9) 24(2.5,2.9) 25(2,2.9) 26(1.5,2.9) 27(1,2.9) 28(0.5,2.9) 29(0,2.9) 30(-0.5,2.9) 31(-1,2.9) 32(-1.5,2.9) 33(-2,2.9) 34(-2.5,2.9) 35(-3,2.9) 36(-3.5,2.9) 37(-4,2.9) 38(-4.5,2.9)
  rect 4.75x2.743 smd: PAD(0,0)
unnamed#2
  round 4.699 hole 3.429 unplated: (0,0)

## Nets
3V3: P1.2 P1.4(N4) R22.1 R23.1 R24.1 R25.1 R26.1 R27.1 U4.5 U5.5
12V: C10.1 C11.1 C12.1 D1.A(P) D4.C R16.1
AGND: ADCCON.7 ADCCON.8 ADCCON.17 ADCCON.18(N9) ADCCON.27 ADCCON.28 BCKGND.1(N1) BSTGND.1(N1) C1N.2(N2) C1P.2(N2) C2.2(N2) C2N.2(N2) C2P.2(N2) C5.2(N2) C7.2(N2) C8.2(N2) C9.2(N2) C11.2(N2) C12.2(N2) CC1B.1 CC2B.2(N2) CDG1.2(N2) CDG2.2(N2) CDM1_1.N(N2) CDM1_2.N(N2) CDM1_3.1 CDM1_4.2(N2) CDM1_5.1 CDM1_6.2(N2) CDM2_1.2(N2) CDM2_2.2(N2) CDM2_3.2(N2) CDM2_4.2(N2) CDM2_5.2(N2) CDM2_6.2(N2) CDM4_1.2(N2) CDM4_2.2(N2) CDM4_3.2(N2) CDM4_4.2(N2) CDM4_5.2(N2) CDM4_6.2(N2) CDM4_7.2(N2) CDM4_8.2(N2) CDM4_9.N(N2) CDM4_X.N(N2) CDRVCC.2(N2) CINVCC.2(N2) CMON1.2(N2) CMON2.2(N2) CSHARE.2(N2) CSS.2(N2) CTMR.1 CV1_B.2(N2) CV2_B.2(N2) DACCON.7 DACCON.8 DACCON.17 DACCON.18(N9) DACCON.27 DACCON.28 M3_1.1 M3_1.2 M3_1.3(S3) M3_2.1 M3_2.2 M3_2.3(S3) M3_3.1 M3_3.2 M3_3.3(S3) M3_4.1 M3_4.2 M3_4.3(S3) P2.1 P3.4(N4) P4.2 P7.2(N2) Q1.2(S) Q2.2(S) R1A.2(N2) R1N.2(N2) R1P.2(N2) R2A.2(N2) R2N.2(N2) R2P.2(N2) R11.2(N2) R17.2(N2) RC1.1 RC2.2(N2) RFB1B.2(N2) RFB2B.2(N2) RMON1.2(N2) RMON2.2(N2) RSYNC.2(N2) RT.2(N2) RUV1B.2(N2) RUV2B.2(N2) U1.PAD U2.4 U3.2 U4.2(V-) U5.2(V-)
V1_ADC: ADCCON.19 U4.1 U4.4
V1D: C1.1 C2.1 CDM1_1.P CDM1_2.P CDM1_3.2(N2) CDM1_4.1 CDM1_5.2(N2) CDM1_6.1 M1B.9 R1.2(N2) RFB1A.1 RSNS1.2 U1.36
V2_ADC: ADCCON.23 U5.1 U5.4
V2D: C6.1 CDM4_1.1 CDM4_2.1 CDM4_3.1 CDM4_4.1 CDM4_5.1 CDM4_6.1 CDM4_7.1 CDM4_8.1 CDM4_9.P CDM4_X.P M4A.9 R14.1 RFB2A.1 RSNS2.F1
BG: M3_1.4 M3_2.4 M3_3.4 M3_4.4 R6.1
BIAS: D1.C D2.C D3.C R9.1 U1.29
BOOSTOUT: BSTOUT.1(N1) CV1_A.1 D3.A(P) M1A.9 R1B.1 R2.2(N2)
BUCKOUT: BCKOUT.1(N1) CV2_A.1 D2.A(P) M4B.9 R2B.1 R13.1
DG1: DV1.2(N2) M1A.1 M1B.1 R3.1 RDG1.1
DG2: M4A.1 M4B.1 R8.2(N2) RDG2.1
DRXN: ADCCON.6 P3.2 P4.11 Q2.1 R24.2(N2) U1.22
DS1: DV1.1 M1A.2 M1A.3 M1A.4 M1A.5 M1A.6 M1A.7 M1A.8(S7) M1B.2 M1B.3 M1B.4 M1B.5 M1B.6 M1B.7 M1B.8(S7) U1.37
DS2: M4A.2 M4A.3 M4A.4 M4A.5 M4A.6 M4A.7 M4A.8(S7) M4B.2 M4B.3 M4B.4 M4B.5 M4B.6 M4B.7 M4B.8(S7) U1.34
EN: ADCCON.5 P4.10 Q1.1 R26.2(N2) U1.33
EXTPWR: ADCCON.29 D5.C DACCON.29 P1.1
FAULT: DACCON.2 DS2.C P4.12 U1.24
FB1: C1.2(N2) FB1CTL.2(N2) RFB1A.2(N2) RFB1B.1 U1.4
FB1_CTL: DACCON.9 FB1CTL.1
FB2: C6.2(N2) FB2CTL.2(N2) RFB2A.2(N2) RFB2B.1 U1.14
FB2_CTL: DACCON.11 FB2CTL.1
IMON1: ADCCON.9 CMON1.1 RMON1.1 U1.5
IMON2: ADCCON.11 CMON2.1 RMON2.1 U1.13
INTVCC: ADCCON.13 CINVCC.1 P5.1 U1.21
ISET1N: C1N.1 R1N.1 RCTL1N.2(N2) U1.6
ISET1N_CTL: DACCON.21 RCTL1N.1
ISET1P: C1P.1 R1P.1 RCTL1P.2(N2) U1.11
ISET1P_CTL: DACCON.19 RCTL1P.1
ISET2N: C2N.1 R2N.1 RCTL2N.2(N2) U1.7
ISET2N_CTL: DACCON.25 RCTL2N.1
ISET2P: C2P.1 R2P.1 RCTL2P.2(N2) U1.12
ISET2P_CTL: DACCON.23 RCTL2P.1
PI_5V: ADCCON.30 C8.1 C9.1 DACCON.30 L2.1 L2.2 P4.1 U3.4 U3.5(VIN)
REPORT: DACCON.1 P4.13 R23.2(N2) U1.25
RX: ADCCON.4 P2.3
SHARE: ADCCON.15 P3.1 R4.1
SNS2N: C4.2(N2) RIN2B.2(N2) U1.19
SNS2P: C4.1 RIN2A.2(N2) U1.18
SYNC: P3.3 P4.9(N9) RSYNC.1 U1.23
T3V3: D5.A(P) P4.3
TX: ADCCON.3 P2.2
UNNAMED_2_ADLT8228_I2_BG: R6.2(N2) U1.27
UNNAMED_2_ADLT8228_I2_BST: R5.2(N2) U1.32
UNNAMED_2_ADLT8228_I2_DG1: R3.2(N2) U1.38
UNNAMED_2_ADLT8228_I2_DG2: R8.1 U1.35
UNNAMED_2_ADLT8228_I2_DRVCC: CDRVCC.1 DBST.A(P) U1.28
UNNAMED_2_ADLT8228_I2_IGND: P7.1 RSHARE.2(N2) U1.20
UNNAMED_2_ADLT8228_I2_ISHARE: P5.2(N2) P6.1 R4.2(N2) U1.17
UNNAMED_2_ADLT8228_I2_RT: RT.1 U1.16
UNNAMED_2_ADLT8228_I2_SNS1N: C3.2(N2) RIN1B.2(N2) U1.2
UNNAMED_2_ADLT8228_I2_SNS1P: C3.1 RIN1A.2(N2) U1.1
UNNAMED_2_ADLT8228_I2_SS: CSS.1 U1.9
UNNAMED_2_ADLT8228_I2_SW: CBST.1 L1.1 M2_1.1 M2_1.2 M2_1.3(S3) M2_2.1 M2_2.2 M2_2.3(S3) M2_3.1 M2_3.2 M2_3.3(S3) M2_4.1 M2_4.2 M2_4.3(S3) M3_1.5 M3_1.6 M3_1.7 M3_1.8 M3_2.5 M3_2.6 M3_2.7 M3_2.8 M3_3.5 M3_3.6 M3_3.7 M3_3.8 M3_4.5 M3_4.6 M3_4.7 M3_4.8 U1.30
UNNAMED_2_ADLT8228_I2_TG: R7.2(N2) U1.31
UNNAMED_2_ADLT8228_I2_TMR: CTMR.2(N2) U1.26
UNNAMED_2_ADLT8228_I2_VC1: CC1A.2(N2) CC1B.2(N2) U1.8
UNNAMED_2_ADLT8228_I2_VC2: CC2A.1 CC2B.1 U1.10(VC2)
UNNAMED_2_CAP_I33_N2: CBST.2(N2) DBST.C R5.1
UNNAMED_2_CAP_I57_N1: CDG1.1 RDG1.2(N2)
UNNAMED_2_CAP_I63_N1: CDG2.1 RDG2.2(N2)
UNNAMED_2_CAP_I97_N1: CC1A.1 RC1.2(N2)
UNNAMED_2_CAP_I106_N2: CC2A.2(N2) RC2.1
UNNAMED_2_CAP_I112_N1: CSHARE.1 P6.2(N2) RSHARE.1
UNNAMED_2_CAP_I268_N1: CDM2_1.1 CDM2_2.1 CDM2_3.1 CDM2_4.1 CDM2_5.1 CDM2_6.1 M2_1.5 M2_1.6 M2_1.7 M2_1.8 M2_2.5 M2_2.6 M2_2.7 M2_2.8 M2_3.5 M2_3.6 M2_3.7 M2_3.8 M2_4.5 M2_4.6 M2_4.7 M2_4.8 RSNS1.1
UNNAMED_2_CAP_I276_N1: CV1_A.2(N2) CV1_B.1
UNNAMED_2_CAP_I281_N1: CV2_A.2(N2) CV2_B.1
UNNAMED_2_IND_I7_N2: L1.2(N2) RSNS2.F2
UNNAMED_2_RES_I42_N1: M2_1.4 M2_2.4 M2_3.4 M2_4.4 R7.1
UNNAMED_2_RES_I147_N1: RIN2A.1 RSNS2.S2
UNNAMED_2_RES_I148_N1: RIN2B.1 RSNS2.S1
UNNAMED_2_RES_I149_N1: RIN1A.1 RSNS1.4(V_2)
UNNAMED_2_RES_I150_N1: RIN1B.1 RSNS1.3
UNNAMED_2_RES_I264_N1: R1.1 R2.1 RUV1A.1
UNNAMED_2_RES_I266_N2: R13.2(N2) R14.2(N2) RUV2A.1
UNNAMED_3_ADLT3010_I70_ADJ: R10.2(N2) R11.1 U2.2
UNNAMED_3_ADLT3010_I70_IN: C5.1 R9.2(N2) U2.5(SHND_N) U2.8
UNNAMED_3_ADLT3010_I70_OUT1: C7.1 P1.3 R10.1 U2.1
UNNAMED_3_CAP_I84_N2: C10.2(N2) R16.2(N2) R17.1 U3.3
UNNAMED_3_DIOSCHOTTKY_I90_P: D4.A(P) L2.3 L2.4(N4) U3.1
UNNAMED_4_AD8677_I30_: R1A.1 R1B.2(N2) U4.3
UNNAMED_4_DIOLED_I3_N: DS3.C Q2.3
UNNAMED_4_DIOLED_I3_P: DS3.A(P) R27.2(N2)
UNNAMED_4_DIOLED_I6_P: DS2.A(P) R25.2(N2)
UNNAMED_4_DIOLED_I17_N: DS1.C Q1.3
UNNAMED_4_DIOLED_I17_P: DS1.A(P) R22.2(N2)
UNNAMED_4_RES_I25_N2: R2A.1 R2B.2(N2) U5.3
UV1: RUV1A.2(N2) RUV1B.1 U1.3 UV1CTL.1
UV1_CTL: DACCON.13 UV1CTL.2(N2)
UV2: RUV2A.2(N2) RUV2B.1 U1.15 UV2CTL.2(N2)
UV2_CTL: DACCON.15 UV2CTL.1

Pads without a net: ADCCON 1 2 10 12 14 16 20 21 22 24 25 26; DACCON 3 4 5 6 10 12 14 16 20 22 24 26; P2 4 5 6 7 8 9 10 11 12 13 14; P4 4 5 6 7 8 14; U2 3 6 7 PAD

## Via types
v1: diameter 0.508, hole 0.254, TOP to BOTTOM, 2528 vias

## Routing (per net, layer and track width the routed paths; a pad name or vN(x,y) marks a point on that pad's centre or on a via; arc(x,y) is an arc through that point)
3V3: length 95.2
  TOP w0.508: R22.1 v1(46.67,28.31) ; R25.1 v1(54.41,28.35) ; v1(56.06,31.78) U5.5 ; U4.5 v1(46.28,31.62) ; R24.1 v1(57.23,29.34) ; R27.1 v1(56.55,28.35) ; R26.1 v1(47.57,29.34)
  TOP w0.762: v1(71.76,25.4) v1(72.54,25.4) 73.05,25.4 76.45,22 110.72,22 113.41,24.69 113.41,38.43 115.57,40.59 115.57,54 117.11,55.55 R23.1
  BOTTOM w0.635: P1.4 54.49,48.5 ; P1.4 54.49,46.24 ; P1.4 55.62,47.37 ; P1.2 55.62,49.91 ; P1.2 54.49,51.04 ; P1.2 54.49,48.78
AGND: length 279.6
  TOP w0.203: U3.2 46.79,54.52 46.99,54.73 v1(46.99,55.19)
  TOP w0.635: 195.44,22.53 P4.2 ; P4.2 197.7,22.53 ; P4.2 196.57,21.39 ; P4.2 196.57,23.66 ; 127.67,47.93 DACCON.8 ; DACCON.8 128.8,46.79 ; DACCON.8 129.93,47.93 ; DACCON.8 128.8,49.06 ; 125.13,47.93 DACCON.7 ; DACCON.7 126.26,46.79 ; DACCON.7 127.39,47.93 ; DACCON.7 126.26,49.06 ; 181.23,35.23 ADCCON.18 ; ADCCON.18 182.37,34.09 ; ADCCON.18 183.5,35.23 ; ADCCON.18 182.37,36.36 ; ADCCON.17 179.83,36.36 ; ADCCON.17 179.83,34.09 ; ADCCON.17 180.96,35.23 ; ADCCON.17 178.69,35.23 ; P2.1 211.81,21.12 ; P2.1 211.81,18.85 ; P2.1 210.68,19.99 ; P2.1 212.94,19.99 ; 181.23,47.93 ADCCON.8 ; ADCCON.8 182.37,46.79 ; ADCCON.8 183.5,47.93 ; 178.69,47.93 ADCCON.7 ; ADCCON.7 180.96,47.93 ; ADCCON.7 179.83,46.79 ; ADCCON.7 179.83,49.06
  L2_GND w0.635: 178.69,35.23 ADCCON.17 ; ADCCON.17 179.83,34.09 ; ADCCON.17 180.96,35.23 ; ADCCON.17 179.83,36.36 ; ADCCON.27 180.73,21.62 ; ADCCON.27 178.92,23.43 ; ADCCON.27 180.73,23.43 ; ADCCON.27 178.92,21.62 ; 182.37,34.09 ADCCON.18 ; ADCCON.18 183.5,35.23 ; ADCCON.18 182.37,36.36 ; ADCCON.18 181.23,35.23 ; DACCON.28 129.7,21.62 ; DACCON.28 127.9,23.43 ; DACCON.28 127.9,21.62 ; DACCON.28 129.7,23.43 ; 195.67,21.62 P4.2 ; P4.2 195.67,23.43 ; P4.2 197.47,23.43 ; P4.2 197.47,21.62 ; P2.1 212.71,20.89 ; P2.1 210.91,20.89 ; P2.1 210.91,19.08 ; P2.1 212.71,19.08 ; BSTGND.1 13.92,76 ; BSTGND.1 9.04,71.12 ; BSTGND.1 18.8,71.12 ; BSTGND.1 13.92,66.24 ; 181.46,21.62 ADCCON.28 ; ADCCON.28 181.46,23.43 ; ADCCON.28 183.27,21.62 ; ADCCON.28 183.27,23.43 ; 125.36,36.13 DACCON.17 ; DACCON.17 127.16,34.32 ; DACCON.17 127.16,36.13 ; DACCON.17 125.36,34.32 ; DACCON.8 129.7,47.02 ; DACCON.8 127.9,48.83 ; DACCON.8 129.7,48.83 ; DACCON.8 127.9,47.02 ; 125.36,48.83 DACCON.7 ; DACCON.7 127.16,47.02 ; DACCON.7 125.36,47.02 ; DACCON.7 127.16,48.83 ; 204.65,70.94 BCKGND.1 ; BCKGND.1 209.52,66.06 ; BCKGND.1 209.52,75.82 ; BCKGND.1 214.4,70.94 ; 125.36,21.62 DACCON.27 ; DACCON.27 127.16,21.62 ; DACCON.27 125.36,23.43 ; DACCON.27 127.16,23.43 ; 181.46,47.02 ADCCON.8 ; ADCCON.8 183.27,48.83 ; ADCCON.8 181.46,48.83 ; ADCCON.8 183.27,47.02 ; ADCCON.7 180.73,48.83 ; ADCCON.7 178.92,47.02 ; ADCCON.7 178.92,48.83 ; ADCCON.7 180.73,47.02 ; DACCON.18 129.7,36.13 ; DACCON.18 127.9,36.13 ; DACCON.18 127.9,34.32 ; DACCON.18 129.7,34.32
  L2_GND w1.27: P3.4 99.36,31.65 98.02,32.99 98.02,40.26
  L3_PWR w0.635: BCKGND.1 209.52,75.82 ; BCKGND.1 209.52,66.06 ; BCKGND.1 214.4,70.94 ; BCKGND.1 204.65,70.94 ; 125.36,47.02 DACCON.7 ; DACCON.7 127.16,48.83 ; DACCON.7 125.36,48.83 ; DACCON.7 127.16,47.02 ; DACCON.8 129.7,48.83 ; DACCON.8 129.7,47.02 ; DACCON.8 127.9,47.02 ; DACCON.8 127.9,48.83 ; 9.04,71.12 BSTGND.1 ; BSTGND.1 18.8,71.12 ; BSTGND.1 13.92,66.24 ; BSTGND.1 13.92,76 ; P2.1 212.71,20.89 ; P2.1 210.91,19.08 ; P2.1 210.91,20.89 ; P2.1 212.71,19.08 ; ADCCON.7 180.73,48.83 ; ADCCON.7 178.92,47.02 ; ADCCON.7 178.92,48.83 ; ADCCON.7 180.73,47.02 ; 181.46,47.02 ADCCON.8 ; ADCCON.8 181.46,48.83 ; ADCCON.8 183.27,47.02 ; ADCCON.8 183.27,48.83
  BOTTOM w0.635: 211.81,18.85 P2.1 ; P2.1 210.68,19.99 ; P2.1 211.81,21.12 ; P2.1 212.94,19.99 ; ADCCON.17 180.96,35.23 ; ADCCON.17 179.83,34.09 ; ADCCON.17 178.69,35.23 ; ADCCON.17 179.83,36.36 ; DACCON.18 128.8,36.36 ; DACCON.18 129.93,35.23 ; DACCON.18 127.67,35.23 ; DACCON.18 128.8,34.09 ; 128.8,21.39 DACCON.28 ; DACCON.28 129.93,22.53 ; DACCON.28 127.67,22.53 ; DACCON.28 128.8,23.66 ; P4.2 197.7,22.53 ; P4.2 196.57,23.66 ; P4.2 195.44,22.53 ; P4.2 196.57,21.39 ; 127.67,47.93 DACCON.8 ; DACCON.8 129.93,47.93 ; DACCON.8 128.8,49.06 ; DACCON.8 128.8,46.79 ; DACCON.27 126.26,23.66 ; DACCON.27 125.13,22.53 ; DACCON.27 127.39,22.53 ; DACCON.27 126.26,21.39 ; 179.83,21.39 ADCCON.27 ; ADCCON.27 180.96,22.53 ; ADCCON.27 178.69,22.53 ; ADCCON.27 179.83,23.66 ; ADCCON.18 183.5,35.23 ; ADCCON.18 181.23,35.23 ; ADCCON.18 182.37,36.36 ; ADCCON.18 182.37,34.09 ; 126.26,46.79 DACCON.7 ; DACCON.7 125.13,47.93 ; DACCON.7 126.26,49.06 ; DACCON.7 127.39,47.93 ; 182.37,21.39 ADCCON.28 ; ADCCON.28 182.37,23.66 ; ADCCON.28 181.23,22.53 ; ADCCON.28 183.5,22.53 ; 126.26,34.09 DACCON.17 ; DACCON.17 126.26,36.36 ; DACCON.17 125.13,35.23 ; DACCON.17 127.39,35.23
  vias: v1(3.48,75.9) v1(3.48,70.82) v1(3.48,65.74) v1(3.48,55.58) v1(3.48,50.5) v1(3.48,45.42) v1(8.56,131.78) v1(8.56,126.7) v1(8.56,75.9) v1(8.56,65.74) v1(8.56,60.66) v1(8.56,55.58) v1(8.56,50.5) v1(8.56,45.42) v1(8.56,25.1) v1(8.56,20.02) v1(8.56,14.94) v1(8.56,9.86) v1(8.56,4.78) v1(8.59,71.12) v1(8.77,72.5) v1(8.77,69.74) v1(9.3,73.79) v1(9.3,68.45) v1(10.15,74.89) v1(10.15,67.35) v1(11.25,75.74) v1(11.25,66.5) v1(12.54,76.27) v1(12.54,65.97) v1(13.64,131.78) v1(13.64,126.7) v1(13.64,86.06) v1(13.64,60.66) v1(13.64,55.58) v1(13.64,50.5) v1(13.64,45.42) v1(13.64,25.1) v1(13.64,20.02) v1(13.64,14.94) v1(13.64,9.86) v1(13.64,4.78) v1(13.92,76.45) v1(13.92,65.79) v1(15.3,76.27) v1(15.3,65.97) v1(15.67,84.53) v1(15.67,83.52) v1(15.67,82.5) v1(15.67,81.48) v1(15.67,80.47) v1(15.67,79.45) v1(16.31,84.02) v1(16.31,83.01) v1(16.31,81.99) v1(16.31,80.98) v1(16.31,79.96) v1(16.59,75.74) v1(16.59,66.5) v1(17.69,74.89) v1(17.69,67.35) v1(18.54,73.79) v1(18.54,68.45) v1(18.72,131.78) v1(18.72,126.7) v1(18.72,86.06) v1(18.72,80.98) v1(18.72,75.9) v1(18.72,65.74) v1(18.72,60.66) v1(18.72,55.58) v1(18.72,50.5) v1(18.72,45.42) v1(18.72,25.1) v1(18.72,20.02) v1(18.72,14.94) v1(18.72,9.86) v1(18.72,4.78) v1(19.07,72.5) v1(19.07,69.74) v1(19.25,71.12) v1(22.02,86.06) v1(23.42,86.06) v1(23.42,85.04) v1(23.8,131.78) v1(23.8,126.7) v1(23.8,80.98) v1(23.8,75.9) v1(23.8,70.82) v1(23.8,65.74) v1(23.8,60.66) v1(23.8,55.58) v1(23.8,50.5) v1(23.8,45.42) v1(23.8,25.1) v1(23.8,20.02) v1(23.8,14.94) v1(23.8,9.86) v1(23.8,4.78) v1(24.05,86.56) v1(24.05,85.55) v1(24.05,84.53) v1(28.88,131.78) v1(28.88,126.7) v1(28.88,80.98) v1(28.88,75.9) v1(28.88,70.82) v1(28.88,65.74) v1(28.88,60.66) v1(28.88,55.58) v1(28.88,50.5) v1(28.88,45.42) v1(28.88,40.34) v1(28.88,25.1) v1(28.88,20.02) v1(28.88,14.94) v1(28.88,9.86) v1(28.88,4.78) v1(30.58,38.38) v1(31.45,46.99) v1(33.25,38.4) v1(33.96,131.78) v1(33.96,126.7) v1(33.96,121.62) v1(33.96,116.54) v1(33.96,111.46) v1(33.96,75.9) v1(33.96,70.82) v1(33.96,65.74) v1(33.96,60.66) v1(33.96,55.58) v1(33.96,50.5) v1(33.96,45.42) v1(33.96,40.34) v1(33.96,30.18) v1(33.96,25.1) v1(33.96,20.02) v1(33.96,14.94) v1(33.96,9.86) v1(33.96,4.78) v1(38.38,30.12) v1(38.4,24.99) v1(39.04,131.78) v1(39.04,126.7) v1(39.04,121.62) v1(39.04,116.54) v1(39.04,111.46) v1(39.04,14.94) v1(39.04,9.86) v1(39.04,4.78) v1(39.83,75.95) v1(39.83,70.74) v1(40.18,71.45) v1(40.44,118.95) v1(40.44,117.68) v1(40.44,116.79) v1(40.44,115.9) v1(40.44,115.01) v1(40.44,114.12) v1(40.44,113.23) v1(40.44,112.34) v1(40.59,70.74) v1(40.82,118.31) v1(40.94,71.45) v1(41.2,118.95) v1(41.35,70.74) v1(41.58,118.31) v1(41.71,71.45) v1(41.96,118.95) v1(42.11,70.74) v1(42.34,118.31) v1(42.47,71.45) v1(42.57,30.76) v1(42.72,118.95) v1(42.88,70.74) v1(43.1,118.31) v1(43.23,71.45) v1(43.48,118.95) v1(43.74,117.68) v1(43.74,116.79) v1(43.74,115.9) v1(43.74,115.01) v1(43.74,114.12) v1(43.74,113.23) v1(43.74,112.34) v1(44.12,131.78) v1(44.12,126.7) v1(44.12,50.5) v1(44.12,14.94) v1(44.12,9.86) v1(44.12,4.78) v1(44.63,21.92) v1(44.88,42.37) v1(44.88,41.35) v1(44.88,40.34) v1(44.88,39.32) v1(45.67,65.28) v1(45.67,62.48) v1(45.72,24.08) v1(48.34,26.77) v1(48.69,75.51) v1(48.95,58.39) v1(49.07,126.7) v1(49.07,121.62) v1(49.07,116.54) v1(49.07,111.46) v1(49.07,70.56) v1(49.12,51.21) v1(49.2,131.78) v1(49.2,74.88) v1(49.2,14.94) v1(49.2,9.86) v1(49.2,4.78) v1(49.5,33.5) v1(49.58,75.51) v1(49.71,38.96) v1(49.96,74.88) v1(50.34,75.51) v1(50.39,24.94) v1(50.6,39.7) v1(50.72,74.88) v1(50.72,38.96) v1(50.85,114.76) v1(51.1,75.51) v1(51.23,114.12) v1(51.49,74.88) v1(51.61,114.76) v1(51.71,28.6) v1(51.87,75.51) v1(51.99,114.12) v1(52.04,31.88) v1(52.07,23.95) v1(52.25,74.88) v1(52.37,114.76) v1(52.63,75.51) v1(52.76,114.12) v1(53.14,114.76) v1(53.14,74.88) v1(53.16,33.78) v1(53.29,43.69) v1(53.29,42.67) v1(53.52,114.12) v1(53.9,114.76) v1(54.15,70.56) v1(54.28,131.78) v1(54.28,126.7) v1(54.28,121.62) v1(54.28,116.54) v1(54.28,14.94) v1(54.28,9.86) v1(54.28,4.78) v1(54.43,55.75) v1(54.79,75.51) v1(55.17,74.88) v1(55.55,75.51) v1(55.55,55.98) v1(55.7,56.79) v1(55.93,74.88) v1(56.06,114.76) v1(56.31,75.51) v1(56.44,114.12) v1(56.69,74.88) v1(56.82,114.76) v1(57.07,75.51) v1(57.2,114.12) v1(57.45,74.88) v1(57.58,114.76) v1(57.84,75.51) v1(57.96,114.12) v1(58.22,74.88) v1(58.24,26.8) v1(58.34,114.76) v1(58.72,114.12) v1(59.11,114.76) v1(59.13,60.68) v1(59.13,26.8) v1(59.23,70.56) v1(59.36,131.78) v1(59.36,126.7) v1(59.36,121.62) v1(59.36,116.54) v1(59.33,33.48) v1(59.36,14.94) v1(59.36,9.86) v1(59.36,4.78) v1(60.25,52.55) v1(61.29,60.68) v1(61.75,90.78) v1(61.7,79.04) v1(61.75,76.17) v1(61.72,73.51) v1(61.77,70.94) v1(61.8,69.47) v1(61.85,32.03) v1(61.95,23.77) v1(62.2,45.57) v1(62.99,33.07) v1(63.75,48.87) v1(63.91,90.8) v1(63.91,76.07) v1(63.91,73.46) v1(63.91,71.02) v1(63.98,79.02) v1(64.06,28.91) v1(64.34,69.67) v1(64.44,131.78) v1(64.44,126.7) v1(64.44,121.62) v1(64.44,116.54) v1(64.39,52.83) v1(64.44,14.94) v1(64.44,9.86) v1(64.44,4.78) v1(65.71,79.86) v1(66.65,71.7) v1(66.73,76.28) v1(67.56,58.98) v1(68.61,29.08) v1(69.16,32.13) v1(69.52,131.78) v1(69.52,126.7) v1(69.52,121.62) v1(69.52,14.94) v1(69.52,9.86) v1(69.52,4.78) v1(69.8,60.96) v1(69.95,71.25) v1(69.95,46.25) v1(70.21,107.77) v1(70.21,82.12) v1(70.97,107.77) v1(70.97,82.12) v1(71.07,76.56) v1(71.6,59.36) v1(71.73,107.77) v1(71.73,82.12) v1(73.2,60.83) v1(74.42,56.52) v1(74.6,131.78) v1(74.6,126.7) v1(74.6,121.62) v1(74.65,73.61) v1(74.6,14.94) v1(74.6,9.86) v1(74.6,4.78) v1(75.41,73.61) v1(75.41,32.33) v1(75.62,58.42) v1(75.84,39.95) v1(76.05,54.86) v1(76.07,45.72) v1(76.17,73.61) v1(76.56,117.04) v1(76.94,73.61) v1(77.06,63.7) v1(77.06,28.93) v1(77.27,56.74) v1(77.27,53.64) v1(77.32,117.04) v1(77.7,73.61) v1(78.08,117.04) v1(78.84,117.04) v1(79.02,46.3) v1(79.43,40.36) v1(79.5,58.95) v1(79.5,51.44) v1(79.68,131.78) v1(79.68,126.7) v1(79.68,121.62) v1(79.68,14.94) v1(79.68,9.86) v1(79.68,4.78) v1(79.88,54.2) v1(80.62,57.05) v1(81.05,49.91) v1(81.51,32.66) v1(81.69,52.35) v1(82.14,70.71) v1(82.17,27.99) v1(82.22,60.3) v1(82.32,107.77) v1(82.35,82.07) v1(83.06,40.06) v1(83.11,107.77) v1(83.11,82.07) v1(83.26,50.83) v1(83.34,48.67) v1(83.87,82.07) v1(83.9,107.8) v1(83.9,55.85) v1(84.66,51.05) v1(84.66,48.46) v1(84.76,131.78) v1(84.76,126.7) v1(84.76,121.62) v1(84.76,14.94) v1(84.76,9.86) v1(84.76,4.78) v1(85.67,40.39) v1(85.8,44.32) v1(86.26,32.89) v1(86.41,64.59) v1(86.97,28.65) v1(87.73,36.4) v1(88.62,116.79) v1(89.38,116.79) v1(89.84,121.62) v1(89.84,14.94) v1(89.84,9.86) v1(89.84,4.78) v1(90.14,116.79) v1(90.45,70.92) v1(90.55,32.82) v1(90.63,40.39) v1(90.7,36.45) v1(90.81,28.5) v1(90.91,116.79) v1(93.9,53.54) v1(93.9,52.53) v1(93.9,51.51) v1(94.34,31.22) v1(94.49,107.77) v1(94.84,53.52) v1(94.84,52.5) v1(94.84,51.49) v1(94.92,121.62) v1(94.92,14.94) v1(94.92,9.86) v1(94.92,4.78) v1(95.28,107.77) v1(95.45,82.12) v1(95.81,53.54) v1(95.81,52.53) v1(95.81,51.51) v1(96.06,107.77) v1(96.22,82.12) v1(96.39,36.47) v1(96.72,53.54) v1(96.72,52.53) v1(96.72,51.51) v1(97.71,53.54) v1(97.71,52.53) v1(97.71,51.51) v1(97.82,41.54) v1(97.87,35.51) v1(97.97,40.31) v1(98.48,28.65) v1(99.59,40.31) v1(99.7,71.3) v1(99.92,33.25) v1(100,121.62) v1(100,116.54) v1(100,14.94) v1(100,9.86) v1(100,4.78) v1(101.47,38.43) v1(102.29,37.62) v1(103.3,29.92) v1(103.39,47.56) v1(103.73,33.25) v1(104.22,64.26) v1(104.44,47.55) v1(104.47,46.36) v1(104.57,39.19) v1(105.08,121.62) v1(105.08,116.54) v1(105.08,14.94) v1(105.08,9.86) v1(105.08,4.78) v1(105.61,46.36) v1(105.69,47.57) v1(105.84,30.05) v1(106.48,51.54) v1(106.45,49) v1(107.52,63.25) v1(107.67,26.01) v1(108.25,52.35) v1(108.25,32.21) v1(108.53,64.13) v1(109.3,30.05) v1(109.45,53.54) v1(109.42,50.42) v1(110.16,121.62) v1(110.16,116.54) v1(110.16,14.94) v1(110.16,9.86) v1(110.16,4.78) v1(110.26,58.12) v1(110.31,42.55) v1(111.23,64.57) v1(111.25,52.27) v1(111.33,42.55) v1(111.76,55.85) v1(111.84,32.31) v1(111.91,25.7) v1(112.34,61.14) v1(114.25,55.22) v1(114.3,71.37) v1(114.5,32.05) v1(114.6,30.15) v1(115.04,59.16) v1(115.24,121.62) v1(115.24,116.54) v1(115.24,14.94) v1(115.24,9.86) v1(115.24,4.78) v1(115.65,35.46) v1(115.75,56.87) v1(115.87,63.14) v1(116.59,60.71) v1(116.81,29.34) v1(117.2,35.51) v1(117.35,32.72) v1(118.01,59) v1(118.34,64.59) v1(118.82,62.89) v1(120.32,121.62) v1(120.32,116.54) v1(120.29,61.32) v1(120.32,14.94) v1(120.32,9.86) v1(120.32,4.78) v1(121.44,69.19) v1(121.41,65.48) v1(122,35.48) v1(122.43,63.47) v1(122.94,61.14) v1(125.3,65.79) v1(125.37,63.65) v1(125.4,121.62) v1(125.4,116.54) v1(125.45,71.75) v1(125.4,14.94) v1(125.4,9.86) v1(125.4,4.78) v1(128.22,65.84) v1(128.3,63.63) v1(130.48,121.62) v1(130.48,116.54) v1(130.48,14.94) v1(130.48,9.86) v1(130.48,4.78) v1(130.91,37.8) v1(130.91,32.33) v1(130.99,30.18) v1(131.27,61.04) v1(131.44,27.46) v1(131.65,63.65) v1(133.17,46.66) v1(133.38,66.78) v1(133.5,42.62) v1(134.34,75.01) v1(135.03,69.67) v1(135,65.79) v1(135.56,131.78) v1(135.56,126.7) v1(135.56,121.62) v1(135.56,116.54) v1(135.56,14.94) v1(135.56,9.86) v1(135.56,4.78) v1(136.32,37.67) v1(136.5,63.47) v1(136.8,35.15) v1(137.26,32.66) v1(137.39,30.43) v1(137.9,42.29) v1(139.04,65.84) v1(139.09,63.68) v1(139.78,27.58) v1(140.28,72.29) v1(140.28,55.6) v1(140.54,59.82) v1(140.64,131.78) v1(140.64,126.7) v1(140.64,121.62) v1(140.64,116.54) v1(140.64,14.94) v1(140.64,9.86) v1(140.64,4.78) v1(140.77,51.87) v1(141.25,47.93) v1(141.86,65.84) v1(141.86,63.65) v1(142.6,41.3) v1(143.43,37.67) v1(144.22,35.18) v1(144.63,32.33) v1(145.41,30.23) v1(145.72,131.78) v1(145.72,126.7) v1(145.72,121.62) v1(145.72,116.54) v1(145.72,14.94) v1(145.72,9.86) v1(145.72,4.78) v1(146.23,56.49) v1(146.76,47.93) v1(146.86,63.6) v1(146.86,45.21) v1(147.09,65.81) v1(147.4,51.79) v1(148.54,59.72) v1(148.87,41.38) v1(149.71,27.25) v1(150.42,63.63) v1(150.52,65.86) v1(150.8,131.78) v1(150.8,126.7) v1(150.8,121.62) v1(150.8,116.54) v1(150.8,70.82) v1(150.8,14.94) v1(150.8,9.86) v1(150.8,4.78) v1(151.1,37.47) v1(152.43,35.26) v1(152.4,32.66) v1(152.76,54.76) v1(153.06,65.86) v1(153.06,48.03) v1(153.16,45.39) v1(153.87,29.95) v1(154.33,63.63) v1(155.58,51.87) v1(155.52,41.35) v1(155.8,65.84) v1(155.88,131.78) v1(155.88,126.7) v1(155.88,121.62) v1(155.88,116.54) v1(155.88,14.94) v1(155.88,9.86) v1(155.88,4.78) v1(156.16,45.52) v1(157.18,63.65) v1(157.15,54.69) v1(157.1,35.1) v1(158.04,27.51) v1(158.39,48.03) v1(158.75,40.92) v1(158.83,30.71) v1(159.44,65.81) v1(160.27,37.67) v1(160.6,63.86) v1(160.96,131.78) v1(160.96,126.7) v1(160.96,121.62) v1(160.96,116.54) v1(160.96,14.94) v1(160.96,9.86) v1(160.96,4.78) v1(161.32,67.67) v1(161.47,42.06) v1(161.93,52.04) v1(162.69,65.99) v1(163.17,69.57) v1(163.19,91.03) v1(163.19,75.51) v1(163.22,71.98) v1(163.83,59.49) v1(164.57,47.96) v1(164.97,68.25) v1(165.23,55.6) v1(165.2,31.29) v1(165.35,76.71) v1(165.35,73.3) v1(165.35,70.74) v1(165.38,91.01) v1(165.4,79.35) v1(166.04,131.78) v1(166.04,126.7) v1(166.04,121.62) v1(166.04,116.54) v1(165.99,41.66) v1(166.04,14.94) v1(166.04,9.86) v1(166.04,4.78) v1(166.22,38.86) v1(167.84,114.55) v1(168.83,27.38) v1(168.96,64.69) v1(168.99,114.55) v1(169.11,76.45) v1(169.7,55.09) v1(170,114.55) v1(170.13,76.45) v1(170.56,41.55) v1(170.48,38.79) v1(171.12,131.78) v1(171.12,126.7) v1(171.12,121.62) v1(171.12,116.54) v1(171.12,70.82) v1(171.12,14.94) v1(171.12,9.86) v1(171.12,4.78) v1(171.27,114.55) v1(171.27,51.97) v1(171.25,47.93) v1(171.4,76.45) v1(172.42,114.55) v1(172.54,76.45) v1(173.43,114.55) v1(173.56,76.45) v1(173.86,32.21) v1(174.96,27.53) v1(175.08,114.55) v1(175.21,76.45) v1(175.97,114.55) v1(176.1,76.45) v1(176.2,131.78) v1(176.2,126.7) v1(176.2,121.62) v1(176.2,70.82) v1(176.2,14.94) v1(176.2,9.86) v1(176.2,4.78) v1(176.56,58.5) v1(176.56,41.55) v1(176.81,39.14) v1(176.89,72.87) v1(176.89,44.75) v1(176.99,114.55) v1(177.11,76.45) v1(178.05,63.12) v1(178.13,28.98) v1(178.64,114.55) v1(178.77,76.45) v1(179.78,114.55) v1(179.91,76.45) v1(180.8,114.55) v1(180.92,76.45) v1(180.92,75.69) v1(181.28,131.78) v1(181.28,126.7) v1(181.28,121.62) v1(181.28,116.54) v1(181.28,70.82) v1(181.28,14.94) v1(181.28,9.86) v1(181.28,4.78) v1(183.59,77.34) v1(183.59,76.33) v1(183.59,75.18) v1(183.72,115.82) v1(183.72,114.68) v1(183.72,113.67) v1(184.23,116.84) v1(184.35,74.3) v1(184.81,40.59) v1(184.91,45.11) v1(184.99,116.84) v1(184.99,38.53) v1(185.04,29.9) v1(185.12,74.3) v1(185.47,65.25) v1(185.75,116.84) v1(185.88,74.3) v1(186.36,131.78) v1(186.36,126.7) v1(186.36,70.82) v1(186.36,14.94) v1(186.36,9.86) v1(186.36,4.78) v1(186.46,35.48) v1(186.51,115.82) v1(186.51,114.68) v1(186.51,113.67) v1(186.51,77.34) v1(186.51,76.33) v1(186.51,75.18) v1(186.51,26.42) v1(186.64,57.73) v1(187.68,43.87) v1(187.76,40.84) v1(188.24,48.29) v1(188.67,29.24) v1(188.95,50.75) v1(189.03,52.96) v1(189.81,38.81) v1(191.44,131.78) v1(191.44,126.7) v1(191.47,112.27) v1(191.44,75.9) v1(191.44,14.94) v1(191.44,9.86) v1(191.44,4.78) v1(191.54,70.79) v1(191.85,50.75) v1(191.97,48.29) v1(192.05,55.17) v1(192,45.72) v1(192,43.76) v1(192.18,64.36) v1(192.23,112.27) v1(192.33,77.67) v1(192.71,77.04) v1(192.99,112.27) v1(193.09,77.67) v1(193.47,77.04) v1(193.62,33.53) v1(193.75,71.22) v1(193.85,77.67) v1(194.23,77.04) v1(194.61,77.67) v1(195,77.04) v1(195.38,77.67) v1(195.55,61.47) v1(196.52,131.78) v1(196.52,126.7) v1(196.52,14.94) v1(196.52,9.86) v1(196.52,4.78) v1(197.05,65.76) v1(199.11,77.83) v1(200.69,34.77) v1(201.52,49.48) v1(201.6,131.78) v1(201.6,126.7) v1(201.6,14.94) v1(201.6,9.86) v1(201.6,4.78) v1(201.85,66.17) v1(203.25,27.53) v1(203.53,22.43) v1(203.81,82.32) v1(203.84,81.33) v1(203.84,80.29) v1(203.84,60.63) v1(204.19,70.94) v1(204.37,72.32) v1(204.37,69.56) v1(204.91,73.61) v1(204.91,68.27) v1(205.75,74.71) v1(205.75,67.17) v1(206.4,131.88) v1(206.4,126.26) v1(206.68,14.94) v1(206.68,9.86) v1(206.68,4.78) v1(206.86,75.56) v1(206.86,66.32) v1(207.87,59.97) v1(208.14,76.09) v1(208.14,65.79) v1(209.52,76.28) v1(209.52,65.61) v1(209.52,45.92) v1(209.58,21.13) v1(210.03,35.51) v1(210.91,76.09) v1(210.91,65.79) v1(211.76,131.78) v1(211.76,126.7) v1(211.76,14.94) v1(211.76,9.86) v1(211.76,4.78) v1(212.19,75.56) v1(212.19,66.32) v1(213.3,74.71) v1(213.3,67.17) v1(213.41,57.91) v1(213.54,83.62) v1(214.14,73.61) v1(214.14,68.27) v1(214.68,72.32) v1(214.68,69.56) v1(214.86,70.94) v1(216.31,40.89) v1(216.84,75.74) v1(216.84,70.66) v1(216.79,45.34) v1(216.84,14.94) v1(216.97,34.04) v1(217.3,65.35) v1(217.3,50.47) v1(217.88,82.12) v1(220.6,80.62) v1(221.01,35.43) v1(221.11,45.01) v1(221.77,54.1) v1(221.92,121.62) v1(221.92,116.54) v1(221.92,101.3) v1(221.92,96.22) v1(221.92,91.14) v1(221.92,75.74) v1(221.92,70.66)
